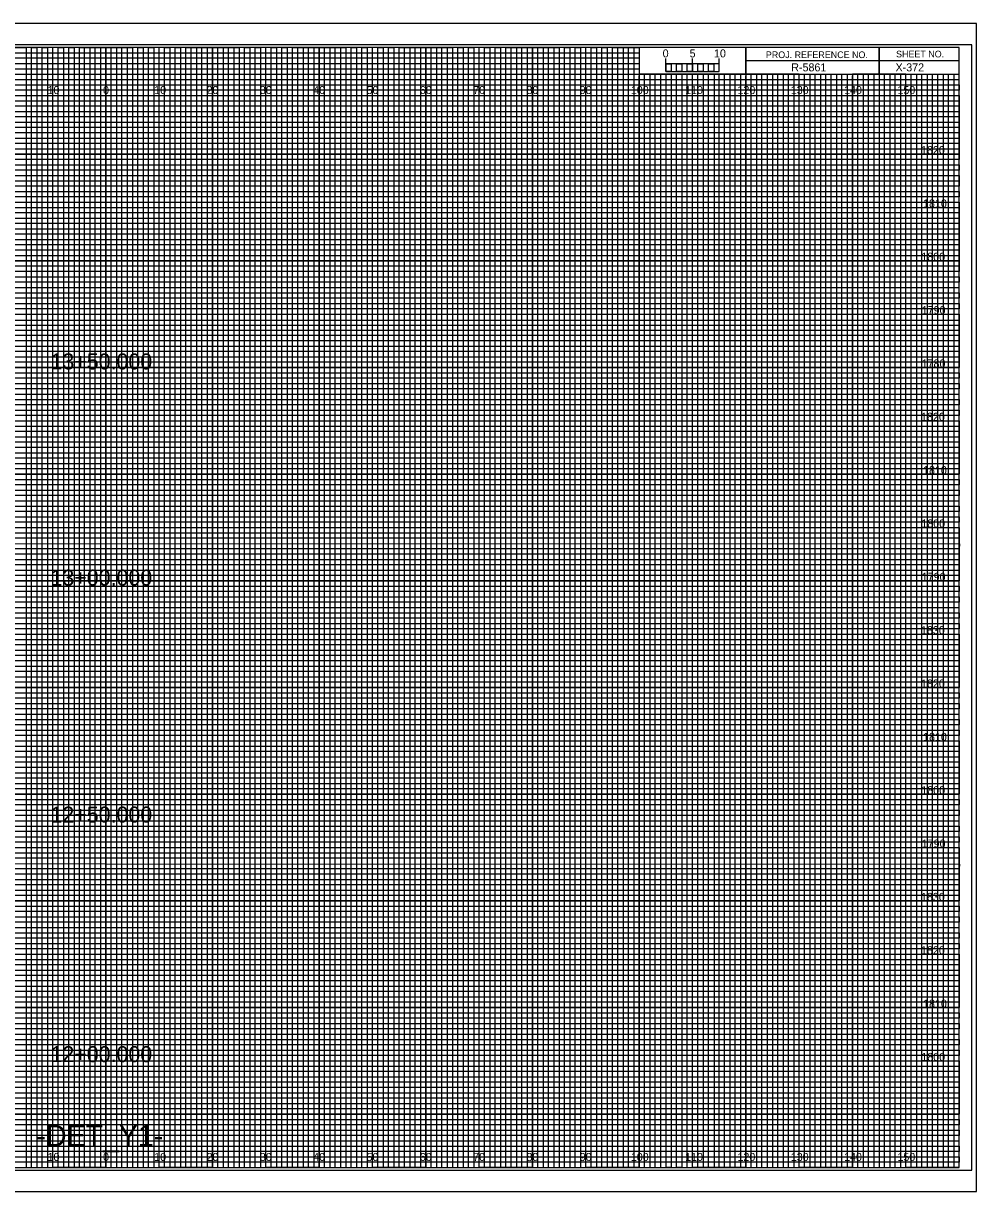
# Model space of a CAD drawing. Extents: x -13 to 323, y -5 to 874.
# Drawn here: x 144.5 to 323.3, y 215.5 to 434.5 of the extents above; entities that cross this region are included whole.
import ezdxf

# ---------------------------------------------------------------- set-up
doc = ezdxf.new("R2010")
doc.units = 0
for name, color, linetype in [('Prop Horizontal Alignment', 7, 'Continuous'), ('Prop XS Alignment Label', 7, 'Continuous'), ('Prop XS Bar Scale Labels', 7, 'Continuous'), ('Prop XS Earthwork Shape', 7, 'Continuous'), ('Prop XS Project Number', 7, 'Continuous'), ('Prop XS Sheet Number', 7, 'Continuous'), ('Raster_Level_0', 7, 'Continuous'), ('Scratch_Level_1', 7, 'Continuous'), ('Scratch_Level_3', 7, 'Continuous'), ('Sheet Cross Section CELL', 7, 'Continuous'), ('Sheet Cross Section Grid Minor 1 CELL', 7, 'Continuous'), ('Sheet Cross Section Grid Minor 2 CELL', 7, 'Continuous'), ('Sheet Cross Section Scale CELL', 7, 'Continuous'), ('Sheet Cutting Line CELL', 7, 'Continuous'), ('Sheet DOT Grid CELL', 7, 'Continuous'), ('Sheet Plot Border Inside CELL', 7, 'Continuous'), ('Sheet Plot Border Outside CELL', 7, 'Continuous')]:
    doc.layers.add(name, color=color, linetype=linetype)

msp = doc.modelspace()

# ---------------------------------------------------------------- linework, layer by layer
at = {"layer": 'Prop XS Earthwork Shape'}
for points in [[(135, 430), (145, 430), (145, 220), (155, 220), (155, 430), (165, 430), (165, 220), (175, 220), (175, 430), (185, 430), (185, 220), (195, 220), (195, 430), (205, 430), (205, 220), (215, 220), (215, 430), (225, 430), (225, 220), (235, 220), (235, 430), (245, 430), (245, 220), (255, 220), (255, 430), (259.93, 430), (260, 430), (260, 425), (264.99, 425), (264.99, 220), (275, 220), (275, 425), (285, 425), (285, 220), (295, 220), (295, 425), (305, 425), (305, 220), (315, 220), (315, 425)], [(0, 425), (275, 425)], [(0, 405), (320, 405), (320, 415), (0, 415)], [(0, 385), (320, 385), (320, 395), (0, 395)], [(0, 365), (320, 365), (320, 375), (0, 375)], [(0, 345), (320, 345), (320, 355), (0, 355)], [(0, 325), (320, 325), (320, 335), (0, 335)], [(0, 305), (320, 305), (320, 315), (0, 315)], [(0, 285), (320, 285), (320, 295), (0, 295)], [(0, 265), (320, 265), (320, 275), (0, 275)], [(0, 245), (320, 245), (320, 255), (0, 255)], [(0, 225), (320, 225), (320, 235), (0, 235)]]:
    msp.add_lwpolyline(points, dxfattribs=at)
at = {"layer": 'Scratch_Level_1'}
for p, q in [((150, 430), (140, 430)), ((150, 220), (150, 430)), ((170, 430), (160, 430)), ((160, 430), (160, 220)), ((170, 220), (170, 430)), ((190, 430), (180, 430)), ((180, 430), (180, 220)), ((190, 220), (190, 430)), ((210, 430), (200, 430)), ((200, 430), (200, 220)), ((210, 220), (210, 430)), ((230, 430), (220, 430)), ((220, 430), (220, 220)), ((230, 220), (230, 430)), ((250, 430), (240, 430)), ((240, 430), (240, 220)), ((250, 220), (250, 430)), ((260, 430), (260, 220)), ((270, 220), (270, 425)), ((290, 425), (280, 425)), ((280, 425), (280, 220)), ((290, 220), (290, 425)), ((310, 425), (300, 425)), ((300, 425), (300, 220)), ((310, 220), (310, 425)), ((160, 220), (150, 220)), ((180, 220), (170, 220)), ((200, 220), (190, 220)), ((220, 220), (210, 220)), ((240, 220), (230, 220)), ((260, 220), (250, 220)), ((280, 220), (270, 220)), ((300, 220), (290, 220)), ((320, 220), (310, 220)), ((320, 220), (320, 220))]:
    msp.add_line(p, q, dxfattribs=at)
for points in [[(0, 420), (320, 420), (320, 410), (0, 410)], [(0, 400), (320, 400), (320, 390), (0, 390)], [(0, 380), (320, 380), (320, 370), (0, 370)], [(0, 360), (320, 360), (320, 350), (0, 350)], [(0, 340), (320, 340), (320, 330), (0, 330)], [(0, 320), (320, 320), (320, 310), (0, 310)], [(0, 300), (320, 300), (320, 290), (0, 290)], [(0, 280), (320, 280), (320, 270), (0, 270)], [(0, 260), (320, 260), (320, 250), (0, 250)], [(0, 240), (320, 240), (320, 230), (0, 230)]]:
    msp.add_lwpolyline(points, dxfattribs=at)
at = {"layer": 'Sheet Cross Section CELL'}
for p, q in [((305, 430), (305, 425)), ((305, 425), (305, 430)), ((280, 427.5), (280, 425)), ((320, 427.49), (280, 427.49)), ((280, 425), (320, 425))]:
    msp.add_line(p, q, dxfattribs=at)
for points in [[(320, 430), (0, 430), (0, 220), (320, 220)], [(280, 430), (260, 430), (260, 425.03), (280, 425.03)], [(320, 430), (280, 430), (280, 425), (320, 425)]]:
    msp.add_lwpolyline(points, close=True, dxfattribs=at)
at = {"layer": 'Sheet Cross Section Grid Minor 1 CELL'}
for p, q in [((0, 429), (260, 429)), ((260, 427.98), (0, 427.98)), ((260, 429), (260, 427.98)), ((0, 427), (260, 427)), ((260, 425.89), (0, 425.89)), ((260, 427), (260, 425.89)), ((0, 424), (320, 424))]:
    msp.add_line(p, q, dxfattribs=at)
for points in [[(0, 423), (270, 423), (320, 423), (320, 422), (0, 422)], [(0, 421), (320, 421), (320, 419), (0, 419)], [(0, 418), (320, 418), (320, 417), (0, 416.98)], [(0, 416), (320, 416), (320, 414), (0, 414)], [(0, 413), (320, 413), (320, 412), (0, 412)], [(0, 411), (320, 411), (320, 409), (0, 409)], [(0, 408), (320, 408), (320, 407), (0, 407)], [(0, 406), (320, 406), (320, 404), (0, 404)], [(0, 403), (320, 403), (320, 402), (0, 402)], [(0, 401), (320, 401), (320, 399), (0, 399)], [(0, 398), (320, 398), (320, 397), (0, 397)], [(0, 396), (320, 396), (320, 393.95), (320, 393), (320, 392), (0, 392)], [(0, 394), (320, 394), (320, 393), (0, 393)], [(0, 391), (320, 391), (320, 389), (0, 389.03)], [(0, 389.03), (320, 389), (320, 388), (0, 388)], [(0, 387), (320, 387), (320, 386), (0, 386)], [(0, 384), (320, 384), (320, 383), (0, 383)], [(0, 382), (320, 382), (320, 381), (0, 381)], [(-0.07, 378.89), (320, 378.89), (320, 377.88), (-0.07, 377.88)], [(0, 377), (320, 377), (320, 376), (0, 376)], [(0, 374), (320, 374), (320, 373), (0, 373)], [(0, 372), (320, 372), (320, 371), (0, 371)], [(0, 369), (320, 369), (320, 368), (0, 368)], [(0, 367), (320, 367), (320, 366), (0, 366)], [(0, 364), (320, 364), (320, 363), (0, 363)], [(0, 362), (320, 362), (320, 361), (0, 361)], [(0, 359), (320, 359), (319.99, 357.98), (0, 358)], [(0, 357), (320, 357), (320, 356), (0, 356)], [(0, 354), (320, 354), (320, 353), (0, 353)], [(0, 352), (320, 352), (320, 351), (0, 351)], [(0, 349), (320, 349), (320, 348), (0, 348)], [(0, 347), (320, 347), (320, 346), (0, 346)], [(0, 344), (320, 344), (320, 343), (0, 343)], [(0, 342), (320, 342), (320, 341), (0, 341)], [(0, 339), (320, 339), (320, 338), (0, 338)], [(0, 336.99), (320.07, 336.91), (320, 336), (0, 336)], [(0, 334), (320, 334), (320, 333), (0, 333)], [(0, 332), (320, 332), (320, 331), (0, 331)], [(0, 329), (320, 329), (320, 328), (0, 328)], [(0, 327), (320, 327), (320, 326), (0, 326)], [(0, 324), (320, 324), (320, 323), (0, 323)], [(0, 322), (320, 322), (320, 321), (0, 321)], [(0, 319), (320, 319), (320, 318), (0, 318)], [(0, 317), (320, 317), (320, 316), (0, 316)], [(0, 314), (320, 314), (320, 313), (0, 313)], [(0, 312), (320, 312), (320, 311), (0, 311)], [(0, 309), (320, 309), (320, 308), (0, 308)], [(0, 307), (320, 307), (320, 306), (0, 306)], [(0, 304), (320, 304), (320, 303), (0, 303)], [(0, 302), (320, 302), (320, 301), (0, 301)], [(0, 299), (320, 299), (319.99, 297.98), (0, 298)], [(0, 297), (320, 297), (320, 296), (0, 296)], [(0, 294), (320, 294), (320, 293), (0, 293)], [(0, 292), (320, 292), (320, 291), (0, 291)], [(0, 289), (320, 289), (320, 288), (0, 288)], [(0, 287), (320, 287), (320, 286), (0, 286)], [(0, 284), (320, 284), (320, 283), (0, 283)], [(0, 282), (320, 282), (320, 281), (0, 281)], [(0, 279), (320, 279), (320, 278), (0, 278)], [(0, 276.99), (320.07, 276.91), (320, 276), (0, 276)], [(0, 274), (320, 274), (320, 273), (0, 273)], [(0, 272), (320, 272), (320, 271), (0, 271)], [(0, 269), (320, 269), (320, 268), (0, 268)], [(0, 267), (320, 267), (320, 266), (0, 266)], [(0, 264), (320, 264), (320, 263), (0, 263)], [(0, 262), (320, 262), (320, 261), (0, 261)], [(0, 259), (320, 259), (320, 258), (0, 258)], [(0, 257), (320, 257), (320, 256), (0, 256)], [(0, 254), (320, 254), (320, 253), (0, 253)], [(0, 252), (320, 252), (320, 251), (0, 251)], [(0, 249), (320, 249), (320, 248), (0, 248)], [(0, 247), (320, 247), (320, 246), (0, 246)], [(0, 244), (320, 244), (320, 243), (0, 243)], [(0, 242), (320, 242), (320, 241), (0, 241)], [(0, 239), (320, 239), (320, 238), (0, 238)], [(0, 237), (320, 237), (320, 236), (0, 236)], [(0, 234), (320, 234), (320, 233), (0, 233)], [(0, 232), (320, 232), (320, 231), (0, 231)], [(0, 229), (320, 229), (320, 228), (0, 228)], [(0, 227), (320, 227), (320, 226), (0, 226)], [(0, 224), (320, 224), (320, 223), (0, 223)], [(0, 222), (320, 222), (320, 221), (0, 221)]]:
    msp.add_lwpolyline(points, dxfattribs=at)
at = {"layer": 'Sheet Cross Section Grid Minor 2 CELL'}
for p, q in [((267, 425), (266.01, 425)), ((266.01, 425), (266.01, 220)), ((267, 220), (267, 425)), ((269, 425), (268, 425)), ((268, 425), (268, 220)), ((269, 220), (269, 425)), ((266.01, 220), (265, 220)), ((268, 220), (267, 220))]:
    msp.add_line(p, q, dxfattribs=at)
for points in [[(145, 220), (146, 220), (146, 430), (147, 430), (147, 220)], [(147, 220), (148, 220), (148, 430), (149, 430), (149, 220)], [(150, 220), (151, 220), (151, 430), (152, 430), (152, 220)], [(152, 220), (153, 220), (153, 430), (154, 430), (154, 220)], [(155, 220), (156, 220), (156, 430), (157, 430), (157, 220)], [(157, 220), (158, 220), (158, 430), (159, 430), (159, 220)], [(160, 220), (161, 220), (161, 430), (162, 430), (162, 220)], [(162, 220), (163, 220), (163, 430), (164, 430), (164, 220)], [(165, 220), (166, 220), (166, 430), (167, 430), (167, 220)], [(167, 220), (168, 220), (168, 430), (169, 430), (169, 220)], [(170, 220), (171, 220), (171, 430), (172, 430), (172, 220)], [(172, 220), (173, 220), (173, 430), (174, 430), (174, 220)], [(175, 220), (176, 220), (176, 430), (177, 430), (177, 220)], [(177, 220), (178, 220), (178, 430), (179, 430), (179, 220)], [(180, 220), (181, 220), (181, 430), (182, 430), (182, 220)], [(182, 220), (183, 220), (183, 430), (184, 430), (184, 220)], [(185, 220), (186, 220), (186, 430), (187, 430), (187, 220)], [(187, 220), (188, 220), (188, 430), (189, 430), (189, 220)], [(190, 220), (191, 220), (191, 430), (192, 430), (192, 220)], [(192, 220), (193, 220), (193, 430), (194, 430), (194, 220)], [(195, 220), (196, 220), (196, 430), (197, 430), (197, 220)], [(197, 220), (198, 220), (198, 430), (199, 430), (199, 220)], [(200, 220), (201, 220), (201, 430), (202, 430), (202, 220)], [(202, 220), (203, 220), (203, 430), (204, 430), (204, 220)], [(205, 220), (206, 220), (206, 430), (207, 430), (207, 220)], [(207, 220), (208, 220), (208, 430), (209, 430), (209, 220)], [(210, 220), (211, 220), (211, 430), (212, 430), (212, 220)], [(212, 220), (213, 220), (213, 430), (214, 430), (214, 220)], [(215, 220), (216, 220), (216, 430), (217, 430), (217, 220)], [(217, 220), (218, 220), (218, 430), (219, 430), (219, 220)], [(220, 220), (221, 220), (221, 430), (222, 430), (222, 220)], [(222, 220), (223, 220), (223, 430), (224, 430), (224, 220)], [(225, 220), (226, 220), (226, 430), (227, 430), (227, 220)], [(227, 220), (228, 220), (228, 430), (229, 430), (229, 220)], [(230, 220), (231, 220), (231, 430), (232, 430), (232, 220)], [(232, 220), (233, 220), (233, 430), (234, 430), (234, 220)], [(235, 220), (236, 220), (236, 430), (237, 430), (237, 220)], [(237, 220), (238, 220), (238, 430), (239, 430), (239, 220)], [(240, 220), (241, 220), (241, 430), (242, 430), (242, 220)], [(242, 220), (243, 220), (243, 430), (244, 430), (244, 220)], [(245, 220), (246, 220), (246, 430), (247, 430), (247, 220)], [(247, 220), (248, 220), (248, 430), (249, 430), (249, 220)], [(250, 220), (251, 220), (251, 430), (252, 430), (252, 220)], [(252, 220), (253, 220), (253, 430), (254, 430), (254, 220)], [(255, 220), (256, 220), (256, 430), (257, 430), (257, 220)], [(257, 220), (258, 220), (258, 430), (259, 430), (259, 220)], [(260, 220), (261, 220), (261, 425), (262.02, 425), (262.02, 220)], [(262, 220), (263, 220), (263, 425), (263.99, 425), (263.99, 220)], [(270, 220), (270.98, 220), (270.98, 425), (272, 425), (272, 220)], [(272, 220), (273, 220), (273, 425), (274.05, 425), (274.05, 220)], [(275, 220), (276, 220), (276, 425), (277, 425), (277, 220)], [(277, 220), (278, 220), (278, 425), (279, 425), (279, 220)], [(280, 220), (281, 220), (281, 425), (282, 425), (282, 220)], [(282, 220), (283, 220), (283, 425), (284, 425), (284, 220)], [(285, 220), (286, 220), (286, 425), (287, 425), (287, 220)], [(287, 220), (288, 220), (288, 425), (289, 425), (289, 220)], [(290, 220), (291, 220), (291, 425), (292, 425), (292, 220)], [(292, 220), (293, 220), (293, 425), (294, 425), (294, 220)], [(295, 220), (296, 220), (296, 425), (297, 425), (297, 220)], [(297, 220), (298, 220), (298, 425), (299, 425), (299, 220)], [(300, 220), (301, 220), (301, 425), (302, 425), (302, 220)], [(302, 220), (303, 220), (303, 425), (304, 425), (304, 220)], [(305, 220), (306, 220), (306, 425), (307, 425), (307, 220)], [(307, 220), (308, 220), (308, 425), (309, 425), (309, 220)], [(310, 220), (311, 220), (311, 425), (312, 425), (312, 220)], [(312, 220), (313, 220), (313, 425), (314, 425), (314, 220)], [(315, 220), (316, 220), (316, 425), (317, 425), (317, 220)], [(317, 220), (318, 220), (318, 425), (319, 425), (319, 220)]]:
    msp.add_lwpolyline(points, dxfattribs=at)
at = {"layer": 'Sheet Cross Section Scale CELL'}
for p, q in [((265, 425.49), (265, 427.9)), ((265, 426.9), (265, 427.9)), ((270, 425.49), (270, 427.9)), ((275, 425.49), (275, 427.9)), ((275, 426.9), (275, 427.9))]:
    msp.add_line(p, q, dxfattribs=at)
for points in [[(275, 426.9), (265, 426.9), (265, 425.49), (275, 425.49)], [(265, 426.9), (266, 426.9), (266, 425.49), (265, 425.49)], [(267, 426.9), (268, 426.9), (268, 425.49), (267, 425.49)], [(269, 426.9), (270, 426.9), (270, 425.49), (269, 425.49)], [(271, 426.9), (272, 426.9), (272, 425.49), (271, 425.49)], [(273, 426.9), (274, 426.9), (274, 425.49), (273, 425.49)]]:
    msp.add_lwpolyline(points, close=True, dxfattribs=at)
at = {"layer": 'Sheet Cutting Line CELL'}
for p, q in [((323.3, 434.5), (-13.4, 434.5)), ((-13.4, 215.5), (323.3, 215.5))]:
    msp.add_line(p, q, dxfattribs=at)
at = {"layer": 'Sheet DOT Grid CELL'}
for p, q in [((150, 220), (150, 430)), ((160, 220), (160, 430)), ((170, 220), (170, 430)), ((180, 220), (180, 430)), ((190, 220), (190, 430)), ((200, 220), (200, 430)), ((210, 220), (210, 430)), ((220, 220), (220, 430)), ((230, 220), (230, 430)), ((240, 220), (240, 430)), ((250, 220), (250, 430)), ((260, 220), (260, 424.69)), ((270, 220), (270, 424.69)), ((280, 220), (280, 424.69)), ((290, 220), (290, 424.69)), ((300, 220), (300, 424.69)), ((310, 220), (310, 424.69)), ((0, 420), (320, 420)), ((0, 410), (320, 410)), ((0, 400), (320, 400)), ((0, 390), (320, 390)), ((0, 380), (320, 380)), ((0, 370), (320, 370)), ((0, 360), (320, 360)), ((0, 350), (320, 350)), ((0, 340), (320, 340)), ((0, 330), (320, 330)), ((0, 320), (320, 320)), ((0, 310), (320, 310)), ((0, 300), (320, 300)), ((0, 290), (320, 290)), ((0, 280), (320, 280)), ((0, 270), (320, 270)), ((0, 260), (320, 260)), ((0, 250), (320, 250)), ((0, 240), (320, 240)), ((0, 230), (320, 230))]:
    msp.add_line(p, q, dxfattribs=at)
at = {"layer": 'Sheet Plot Border Inside CELL'}
msp.add_lwpolyline([(-10.8, 219.5), (322.4, 219.5), (322.4, 430.5), (-10.8, 430.5)], close=True, dxfattribs=at)
at = {"layer": 'Sheet Plot Border Outside CELL'}
msp.add_lwpolyline([(-13.4, 215.5), (323.3, 215.5), (323.3, 434.5), (-13.4, 434.5)], close=True, dxfattribs=at)

# ---------------------------------------------------------------- texts
at = {"layer": 'Prop Horizontal Alignment'}
for s, p in [('13+50.000', (149.59, 369.63)), ('13+00.000', (149.59, 329.1)), ('12+50.000', (149.59, 284.68)), ('12+00.000', (149.59, 239.77))]:
    msp.add_text(s, height=3, dxfattribs=at).set_placement(p)
at = {"layer": 'Prop XS Alignment Label'}
msp.add_text('-DET_Y1-', height=4, dxfattribs=at).set_placement((146.97, 224))
at = {"layer": 'Prop XS Bar Scale Labels'}
for s, p in [('5', (269.47, 428.12)), ('10', (274.04, 428.12))]:
    msp.add_text(s, height=1.5, dxfattribs=at).set_placement(p)
at = {"layer": 'Prop XS Project Number'}
msp.add_text('R-5861', height=1.5, dxfattribs=at).set_placement((288.53, 425.5))
at = {"layer": 'Prop XS Sheet Number'}
msp.add_text('X-372', height=1.5, dxfattribs=at).set_placement((308.09, 425.5))
at = {"layer": 'Raster_Level_0'}
for s, p in [('10', (149.04, 421.25)), ('0', (159.45, 421.25)), ('0', (159.45, 421.25)), ('10', (169.04, 421.25)), ('20', (178.86, 421.25)), ('30', (188.86, 421.25)), ('40', (198.86, 421.25)), ('50', (208.86, 421.25)), ('60', (218.86, 421.25)), ('70', (228.86, 421.25)), ('80', (238.86, 421.25)), ('90', (248.86, 421.25)), ('100', (258.44, 421.25)), ('110', (268.62, 421.25)), ('120', (278.44, 421.25)), ('130', (288.44, 421.25)), ('140', (298.44, 421.25)), ('150', (308.44, 421.25)), ('10', (149.04, 221.25)), ('0', (159.45, 221.25)), ('0', (159.45, 221.25)), ('10', (169.04, 221.25)), ('20', (178.86, 221.25)), ('30', (188.86, 221.25)), ('40', (198.86, 221.25)), ('50', (208.86, 221.25)), ('60', (218.86, 221.25)), ('70', (228.86, 221.25)), ('80', (238.86, 221.25)), ('90', (248.86, 221.25)), ('100', (258.44, 221.25)), ('110', (268.62, 221.25)), ('120', (278.44, 221.25)), ('130', (288.44, 221.25)), ('140', (298.44, 221.25)), ('150', (308.44, 221.25))]:
    msp.add_text(s, height=1.5, dxfattribs=at).set_placement(p)
at = {"layer": 'Scratch_Level_3'}
for s, p in [('1820', (312.87, 410)), ('1810', (313.25, 400)), ('1800', (312.92, 390)), ('1790', (313, 380)), ('1780', (312.98, 370)), ('1820', (312.87, 360)), ('1810', (313.25, 350)), ('1800', (312.92, 340)), ('1790', (313, 330)), ('1830', (312.86, 320)), ('1820', (312.87, 310)), ('1810', (313.25, 300)), ('1800', (312.92, 290)), ('1790', (313, 280)), ('1830', (312.86, 270)), ('1820', (312.87, 260)), ('1810', (313.25, 250)), ('1800', (312.92, 240))]:
    msp.add_text(s, height=1.5, dxfattribs=at).set_placement(p)
at = {"layer": 'Sheet Cross Section CELL'}
for s, p in [('PROJ. REFERENCE NO.', (283.77, 427.99)), ('SHEET NO.', (308.19, 428.12))]:
    msp.add_text(s, height=1.25, dxfattribs=at).set_placement(p)
at = {"layer": 'Sheet Cross Section Scale CELL'}
msp.add_text('0', height=1.5, dxfattribs=at).set_placement((264.41, 428.12))

doc.saveas('drawing.dxf')
